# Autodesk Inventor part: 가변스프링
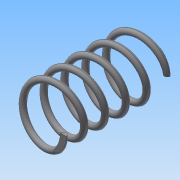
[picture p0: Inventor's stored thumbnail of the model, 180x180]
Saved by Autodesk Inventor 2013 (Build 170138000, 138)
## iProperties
Created: 2017-02
Part Number: 가변스프링
Material: Generic
Document SubType Name: Modeling
Designer: Administrator
Density: 1 g/cm^3
Author: Administrator
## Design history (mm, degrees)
sketch "스케치1"
  geometry: L1 (0, 0)-(8.5, 0); L2 (8.5, 0)-(8.5, 35); L3 (8.5, 35)-(0, 35); L4 (0, 35)-(0, 0); C1 r 1 at (8.5, 0)
  constraints: 8 end point, 2 parallel, 1 centre point, 1 coincident, 1 horizontal, 1 perpendicular
  dimensions: "d0" = 17 diameter of L2 L4; "d2" = 35 distance of L1.end L2.end (derived); "d3" = 2 diameter of C1
feature "코일1" sketch "스케치1" pitch "d4" = 10; turns "d6" = 5; dims "d5" = 35 (= d2), "d7" = 0, angle "d8" = 90 deg, angle "d9" = 90 deg, "d10" = 0, "d11" = 0
sketch "스케치2"
  geometry: L1 (0, -14.823)-(35, -14.823); L2 (35, -14.823)-(35, 14.823); L3 (35, 14.823)-(0, 14.823); L4 (0, 14.823)-(0, -14.823); 3 further points
  constraints: 8 end point, 3 midpoint, 2 parallel, 1 horizontal, 1 horizontal alignment, 1 perpendicular
  dimensions: "d12" = 29.64624 distance of L1.end L2.end
extrude "돌출1" sketch "스케치2" stored distance "d14" = 0; taper "d15" = 0 deg
node "솔리드1"
